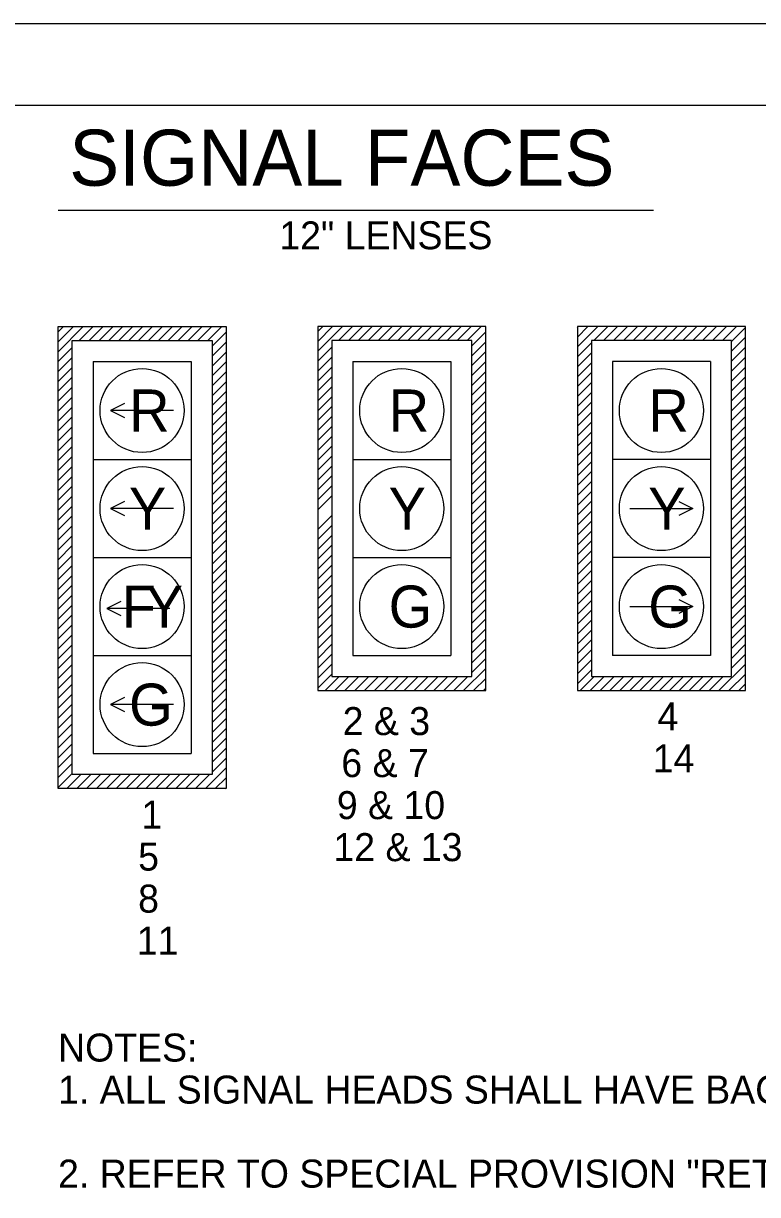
# Model space of a CAD drawing. Extents: x 659404 to 660404, y 642315 to 642955.
# Drawn here: x 659580.3 to 659685.2, y 642787.9 to 642955.1 of the extents above; entities that cross this region are included whole.
import ezdxf

# ---------------------------------------------------------------- set-up
doc = ezdxf.new("R2010")
doc.units = 0
for name, color, linetype in [('R_Border', 7, 'Continuous'), ('R_No Plot', 7, 'Continuous'), ('T_Drafting', 7, 'Continuous'), ('T_Notes', 7, 'Continuous')]:
    doc.layers.add(name, color=color, linetype=linetype)

msp = doc.modelspace()

# ---------------------------------------------------------------- linework, layer by layer
at = {"layer": 'R_Border'}
msp.add_line((659440.89, 642943.46), (660389.43, 642943.46), dxfattribs=at)
at = {"layer": 'R_No Plot'}
msp.add_line((659403.69, 642955.15), (660403.69, 642955.15), dxfattribs=at)
msp.add_lwpolyline([(659403.67, 642955.15), (660403.69, 642955.15), (660403.69, 642315.13), (659403.67, 642315.13)], close=True, dxfattribs=at)
at = {"layer": 'T_Drafting'}
for p, q in [((659585.24, 642845.87), (659585.24, 642911.87)), ((659585.24, 642911.87), (659609.24, 642911.87)), ((659585.24, 642908.27), (659588.85, 642911.87)), ((659585.24, 642909.68), (659587.44, 642911.87)), ((659585.24, 642911.09), (659586.02, 642911.87)), ((659588.26, 642909.87), (659590.26, 642911.87)), ((659589.68, 642909.87), (659591.68, 642911.87)), ((659591.09, 642909.87), (659593.09, 642911.87)), ((659592.51, 642909.87), (659594.51, 642911.87)), ((659593.92, 642909.87), (659595.92, 642911.87)), ((659595.33, 642909.87), (659597.33, 642911.87)), ((659596.75, 642909.87), (659598.75, 642911.87)), ((659598.16, 642909.87), (659600.16, 642911.87)), ((659599.58, 642909.87), (659601.58, 642911.87)), ((659600.99, 642909.87), (659602.99, 642911.87)), ((659602.41, 642909.87), (659604.41, 642911.87)), ((659603.82, 642909.87), (659605.82, 642911.87)), ((659605.23, 642909.87), (659607.23, 642911.87)), ((659606.65, 642909.87), (659608.65, 642911.87)), ((659609.24, 642911.87), (659609.24, 642845.87)), ((659646.34, 642911.87), (659622.34, 642911.87)), ((659622.34, 642911.87), (659622.34, 642859.87)), ((659622.34, 642908.33), (659625.88, 642911.87)), ((659622.34, 642909.74), (659624.47, 642911.87)), ((659622.34, 642911.15), (659623.05, 642911.87)), ((659625.3, 642909.87), (659627.3, 642911.87)), ((659626.71, 642909.87), (659628.71, 642911.87)), ((659628.12, 642909.87), (659630.12, 642911.87)), ((659629.54, 642909.87), (659631.54, 642911.87)), ((659630.95, 642909.87), (659632.95, 642911.87)), ((659632.37, 642909.87), (659634.37, 642911.87)), ((659633.78, 642909.87), (659635.78, 642911.87)), ((659635.2, 642909.87), (659637.2, 642911.87)), ((659636.61, 642909.87), (659638.61, 642911.87)), ((659638.02, 642909.87), (659640.02, 642911.87)), ((659639.44, 642909.87), (659641.44, 642911.87)), ((659640.85, 642909.87), (659642.85, 642911.87)), ((659642.27, 642909.87), (659644.27, 642911.87)), ((659643.68, 642909.87), (659645.68, 642911.87)), ((659646.34, 642859.87), (659646.34, 642911.87)), ((659683.43, 642911.87), (659659.43, 642911.87)), ((659659.43, 642911.87), (659659.43, 642859.87)), ((659659.43, 642908.95), (659662.35, 642911.87)), ((659659.43, 642910.36), (659660.94, 642911.87)), ((659659.43, 642911.78), (659659.52, 642911.87)), ((659661.77, 642909.87), (659663.77, 642911.87)), ((659663.18, 642909.87), (659665.18, 642911.87)), ((659664.6, 642909.87), (659666.6, 642911.87)), ((659666.01, 642909.87), (659668.01, 642911.87)), ((659667.42, 642909.87), (659669.42, 642911.87)), ((659668.84, 642909.87), (659670.84, 642911.87)), ((659670.25, 642909.87), (659672.25, 642911.87)), ((659671.67, 642909.87), (659673.67, 642911.87)), ((659673.08, 642909.87), (659675.08, 642911.87)), ((659674.5, 642909.87), (659676.5, 642911.87)), ((659675.91, 642909.87), (659677.91, 642911.87)), ((659677.32, 642909.87), (659679.32, 642911.87)), ((659678.74, 642909.87), (659680.74, 642911.87)), ((659680.15, 642909.87), (659682.15, 642911.87)), ((659681.43, 642909.73), (659683.43, 642911.73)), ((659683.43, 642859.87), (659683.43, 642911.87)), ((659607.24, 642909.05), (659609.24, 642911.05)), ((659607.24, 642907.64), (659609.24, 642909.64)), ((659644.34, 642909.11), (659646.34, 642911.11)), ((659644.34, 642907.7), (659646.34, 642909.7)), ((659659.43, 642907.53), (659661.43, 642909.53)), ((659681.43, 642908.32), (659683.43, 642910.32)), ((659585.24, 642906.85), (659587.24, 642908.85)), ((659607.24, 642906.22), (659609.24, 642908.22)), ((659622.34, 642906.91), (659624.34, 642908.91)), ((659644.34, 642906.28), (659646.34, 642908.28)), ((659659.43, 642906.12), (659661.43, 642908.12)), ((659681.43, 642906.91), (659683.43, 642908.91)), ((659585.24, 642905.44), (659587.24, 642907.44)), ((659590.24, 642906.87), (659604.24, 642906.87)), ((659590.24, 642906.87), (659590.24, 642892.87)), ((659604.24, 642906.87), (659604.24, 642892.87)), ((659607.24, 642904.81), (659609.24, 642906.81)), ((659622.34, 642905.5), (659624.34, 642907.5)), ((659627.34, 642906.87), (659641.34, 642906.87)), ((659627.34, 642906.87), (659627.34, 642892.87)), ((659641.34, 642906.87), (659641.34, 642892.87)), ((659644.34, 642904.87), (659646.34, 642906.87)), ((659659.43, 642904.7), (659661.43, 642906.7)), ((659678.43, 642906.87), (659664.43, 642906.87)), ((659664.43, 642906.87), (659664.43, 642892.87)), ((659678.43, 642906.87), (659678.43, 642892.87)), ((659681.43, 642905.49), (659683.43, 642907.49)), ((659585.24, 642904.02), (659587.24, 642906.02)), ((659585.24, 642902.61), (659587.24, 642904.61)), ((659607.24, 642903.4), (659609.24, 642905.4)), ((659622.34, 642904.08), (659624.34, 642906.08)), ((659622.34, 642902.67), (659624.34, 642904.67)), ((659644.34, 642903.46), (659646.34, 642905.46)), ((659659.43, 642903.29), (659661.43, 642905.29)), ((659681.43, 642904.08), (659683.43, 642906.08)), ((659681.43, 642902.66), (659683.43, 642904.66)), ((659585.24, 642901.19), (659587.24, 642903.19)), ((659607.24, 642901.98), (659609.24, 642903.98)), ((659622.34, 642901.25), (659624.34, 642903.25)), ((659644.34, 642902.04), (659646.34, 642904.04)), ((659659.43, 642901.88), (659661.43, 642903.88)), ((659681.43, 642901.25), (659683.43, 642903.25)), ((659585.24, 642899.78), (659587.24, 642901.78)), ((659607.24, 642900.57), (659609.24, 642902.57)), ((659607.24, 642899.15), (659609.24, 642901.15)), ((659622.34, 642899.84), (659624.34, 642901.84)), ((659644.34, 642900.63), (659646.34, 642902.63)), ((659644.34, 642899.21), (659646.34, 642901.21)), ((659659.43, 642900.46), (659661.43, 642902.46)), ((659681.43, 642899.83), (659683.43, 642901.83)), ((659585.24, 642898.37), (659587.24, 642900.37)), ((659601.74, 642899.87), (659592.74, 642899.87)), ((659607.24, 642897.74), (659609.24, 642899.74)), ((659622.34, 642898.43), (659624.34, 642900.43)), ((659644.34, 642897.8), (659646.34, 642899.8)), ((659659.43, 642899.05), (659661.43, 642901.05)), ((659659.43, 642897.63), (659661.43, 642899.63)), ((659681.43, 642898.42), (659683.43, 642900.42)), ((659585.24, 642896.95), (659587.24, 642898.95)), ((659607.24, 642896.32), (659609.24, 642898.32)), ((659622.34, 642897.01), (659624.34, 642899.01)), ((659644.34, 642896.38), (659646.34, 642898.38)), ((659659.43, 642896.22), (659661.43, 642898.22)), ((659681.43, 642897.01), (659683.43, 642899.01)), ((659585.24, 642895.54), (659587.24, 642897.54)), ((659607.24, 642894.91), (659609.24, 642896.91)), ((659622.34, 642895.6), (659624.34, 642897.6)), ((659622.34, 642894.18), (659624.34, 642896.18)), ((659644.34, 642894.97), (659646.34, 642896.97)), ((659659.43, 642894.8), (659661.43, 642896.8)), ((659681.43, 642895.59), (659683.43, 642897.59)), ((659681.43, 642894.18), (659683.43, 642896.18)), ((659585.24, 642894.12), (659587.24, 642896.12)), ((659585.24, 642892.71), (659587.24, 642894.71)), ((659607.24, 642893.5), (659609.24, 642895.5)), ((659622.34, 642892.77), (659624.34, 642894.77)), ((659644.34, 642893.56), (659646.34, 642895.56)), ((659659.43, 642893.39), (659661.43, 642895.39)), ((659681.43, 642892.76), (659683.43, 642894.76)), ((659585.24, 642891.29), (659587.24, 642893.29)), ((659590.24, 642892.87), (659604.24, 642892.87)), ((659590.24, 642892.87), (659590.24, 642878.87)), ((659604.24, 642892.87), (659604.24, 642878.87)), ((659607.24, 642892.08), (659609.24, 642894.08)), ((659622.34, 642891.35), (659624.34, 642893.35)), ((659627.34, 642892.87), (659641.34, 642892.87)), ((659627.34, 642892.87), (659627.34, 642878.87)), ((659641.34, 642892.87), (659641.34, 642878.87)), ((659644.34, 642892.14), (659646.34, 642894.14)), ((659659.43, 642891.98), (659661.43, 642893.98)), ((659678.43, 642892.87), (659664.43, 642892.87)), ((659664.43, 642892.87), (659664.43, 642878.87)), ((659678.43, 642892.87), (659678.43, 642878.87)), ((659681.43, 642891.35), (659683.43, 642893.35)), ((659585.24, 642889.88), (659587.24, 642891.88)), ((659607.24, 642890.67), (659609.24, 642892.67)), ((659607.24, 642889.25), (659609.24, 642891.25)), ((659622.34, 642889.94), (659624.34, 642891.94)), ((659644.34, 642890.73), (659646.34, 642892.73)), ((659644.34, 642889.31), (659646.34, 642891.31)), ((659659.43, 642890.56), (659661.43, 642892.56)), ((659659.43, 642889.15), (659661.43, 642891.15)), ((659681.43, 642889.93), (659683.43, 642891.93)), ((659585.24, 642888.47), (659587.24, 642890.47)), ((659607.24, 642887.84), (659609.24, 642889.84)), ((659622.34, 642888.53), (659624.34, 642890.53)), ((659644.34, 642887.9), (659646.34, 642889.9)), ((659659.43, 642887.73), (659661.43, 642889.73)), ((659681.43, 642888.52), (659683.43, 642890.52)), ((659585.24, 642887.05), (659587.24, 642889.05)), ((659607.24, 642886.42), (659609.24, 642888.42)), ((659622.34, 642887.11), (659624.34, 642889.11)), ((659644.34, 642886.48), (659646.34, 642888.48)), ((659659.43, 642886.32), (659661.43, 642888.32)), ((659681.43, 642887.11), (659683.43, 642889.11)), ((659585.24, 642885.64), (659587.24, 642887.64)), ((659585.24, 642884.22), (659587.24, 642886.22)), ((659607.24, 642885.01), (659609.24, 642887.01)), ((659622.34, 642885.7), (659624.34, 642887.7)), ((659644.34, 642885.07), (659646.34, 642887.07)), ((659659.43, 642884.91), (659661.43, 642886.91)), ((659681.43, 642885.69), (659683.43, 642887.69)), ((659681.43, 642884.28), (659683.43, 642886.28)), ((659585.24, 642882.81), (659587.24, 642884.81)), ((659601.74, 642885.87), (659592.74, 642885.87)), ((659607.24, 642883.6), (659609.24, 642885.6)), ((659622.34, 642882.87), (659624.34, 642884.87)), ((659644.34, 642883.66), (659646.34, 642885.66)), ((659659.43, 642883.49), (659661.43, 642885.49)), ((659666.93, 642885.87), (659675.93, 642885.87)), ((659681.43, 642882.86), (659683.43, 642884.86)), ((659585.24, 642881.4), (659587.24, 642883.4)), ((659607.24, 642882.18), (659609.24, 642884.18)), ((659607.24, 642880.77), (659609.24, 642882.77)), ((659622.34, 642881.46), (659624.34, 642883.46)), ((659644.34, 642882.24), (659646.34, 642884.24)), ((659644.34, 642880.83), (659646.34, 642882.83)), ((659659.43, 642882.08), (659661.43, 642884.08)), ((659681.43, 642881.45), (659683.43, 642883.45)), ((659585.24, 642879.98), (659587.24, 642881.98)), ((659607.24, 642879.35), (659609.24, 642881.35)), ((659622.34, 642880.04), (659624.34, 642882.04)), ((659644.34, 642879.41), (659646.34, 642881.41)), ((659659.43, 642880.66), (659661.43, 642882.66)), ((659659.43, 642879.25), (659661.43, 642881.25)), ((659681.43, 642880.04), (659683.43, 642882.04)), ((659585.24, 642878.57), (659587.24, 642880.57)), ((659607.24, 642877.94), (659609.24, 642879.94)), ((659622.34, 642878.63), (659624.34, 642880.63)), ((659644.34, 642878), (659646.34, 642880)), ((659659.43, 642877.83), (659661.43, 642879.83)), ((659681.43, 642878.62), (659683.43, 642880.62)), ((659585.24, 642877.15), (659587.24, 642879.15)), ((659585.24, 642875.74), (659587.24, 642877.74)), ((659590.24, 642878.87), (659604.24, 642878.87)), ((659590.24, 642878.87), (659590.24, 642864.87)), ((659604.24, 642878.87), (659604.24, 642864.87)), ((659607.24, 642876.52), (659609.24, 642878.52)), ((659622.34, 642877.21), (659624.34, 642879.21)), ((659622.34, 642875.8), (659624.34, 642877.8)), ((659627.34, 642878.87), (659641.34, 642878.87)), ((659627.34, 642878.87), (659627.34, 642864.87)), ((659641.34, 642878.87), (659641.34, 642864.87)), ((659644.34, 642876.59), (659646.34, 642878.59)), ((659659.43, 642876.42), (659661.43, 642878.42)), ((659678.43, 642878.87), (659664.43, 642878.87)), ((659664.43, 642878.87), (659664.43, 642864.87)), ((659678.43, 642878.87), (659678.43, 642864.87)), ((659681.43, 642877.21), (659683.43, 642879.21)), ((659681.43, 642875.79), (659683.43, 642877.79)), ((659585.24, 642874.32), (659587.24, 642876.32)), ((659607.24, 642875.11), (659609.24, 642877.11)), ((659622.34, 642874.38), (659624.34, 642876.38)), ((659644.34, 642875.17), (659646.34, 642877.17)), ((659659.43, 642875.01), (659661.43, 642877.01)), ((659681.43, 642874.38), (659683.43, 642876.38)), ((659585.24, 642872.91), (659587.24, 642874.91)), ((659607.24, 642873.7), (659609.24, 642875.7)), ((659622.34, 642872.97), (659624.34, 642874.97)), ((659644.34, 642873.76), (659646.34, 642875.76)), ((659659.43, 642873.59), (659661.43, 642875.59)), ((659681.43, 642872.96), (659683.43, 642874.96)), ((659585.24, 642871.5), (659587.24, 642873.5)), ((659607.24, 642872.28), (659609.24, 642874.28)), ((659607.24, 642870.87), (659609.24, 642872.87)), ((659622.34, 642871.56), (659624.34, 642873.56)), ((659644.34, 642872.34), (659646.34, 642874.34)), ((659644.34, 642870.93), (659646.34, 642872.93)), ((659659.43, 642872.18), (659661.43, 642874.18)), ((659659.43, 642870.76), (659661.43, 642872.76)), ((659681.43, 642871.55), (659683.43, 642873.55)), ((659585.24, 642870.08), (659587.24, 642872.08)), ((659601.22, 642871.59), (659592.22, 642871.59)), ((659607.24, 642869.45), (659609.24, 642871.45)), ((659622.34, 642870.14), (659624.34, 642872.14)), ((659644.34, 642869.51), (659646.34, 642871.51)), ((659659.43, 642869.35), (659661.43, 642871.35)), ((659666.93, 642871.87), (659675.93, 642871.87)), ((659681.43, 642870.14), (659683.43, 642872.14)), ((659585.24, 642868.67), (659587.24, 642870.67)), ((659607.24, 642868.04), (659609.24, 642870.04)), ((659622.34, 642868.73), (659624.34, 642870.73)), ((659644.34, 642868.1), (659646.34, 642870.1)), ((659659.43, 642867.93), (659661.43, 642869.93)), ((659681.43, 642868.72), (659683.43, 642870.72)), ((659585.24, 642867.25), (659587.24, 642869.25)), ((659585.24, 642865.84), (659587.24, 642867.84)), ((659607.24, 642866.63), (659609.24, 642868.63)), ((659622.34, 642867.31), (659624.34, 642869.31)), ((659622.34, 642865.9), (659624.34, 642867.9)), ((659644.34, 642866.69), (659646.34, 642868.69)), ((659659.43, 642866.52), (659661.43, 642868.52)), ((659681.43, 642867.31), (659683.43, 642869.31)), ((659681.43, 642865.89), (659683.43, 642867.89)), ((659585.24, 642864.42), (659587.24, 642866.42)), ((659607.24, 642865.21), (659609.24, 642867.21)), ((659622.34, 642864.48), (659624.34, 642866.48)), ((659644.34, 642865.27), (659646.34, 642867.27)), ((659659.43, 642865.11), (659661.43, 642867.11)), ((659681.43, 642864.48), (659683.43, 642866.48)), ((659585.24, 642863.01), (659587.24, 642865.01)), ((659590.24, 642864.87), (659604.24, 642864.87)), ((659590.24, 642864.87), (659590.24, 642850.87)), ((659604.24, 642864.87), (659604.24, 642850.87)), ((659607.24, 642863.8), (659609.24, 642865.8)), ((659607.24, 642862.38), (659609.24, 642864.38)), ((659622.34, 642863.07), (659624.34, 642865.07)), ((659627.34, 642864.87), (659641.34, 642864.87)), ((659644.34, 642863.86), (659646.34, 642865.86)), ((659644.34, 642862.44), (659646.34, 642864.44)), ((659659.43, 642863.69), (659661.43, 642865.69)), ((659678.43, 642864.87), (659664.43, 642864.87)), ((659681.43, 642863.06), (659683.43, 642865.06)), ((659585.24, 642861.6), (659587.24, 642863.6)), ((659607.24, 642860.97), (659609.24, 642862.97)), ((659622.34, 642861.66), (659624.34, 642863.66)), ((659643.18, 642859.87), (659646.34, 642863.03)), ((659659.43, 642862.28), (659661.43, 642864.28)), ((659659.43, 642860.86), (659661.43, 642862.86)), ((659679.65, 642859.87), (659683.43, 642863.65)), ((659585.24, 642860.18), (659587.24, 642862.18)), ((659607.24, 642859.55), (659609.24, 642861.55)), ((659622.34, 642860.24), (659624.34, 642862.24)), ((659623.38, 642859.87), (659625.38, 642861.87)), ((659624.79, 642859.87), (659626.79, 642861.87)), ((659626.21, 642859.87), (659628.21, 642861.87)), ((659627.62, 642859.87), (659629.62, 642861.87)), ((659629.04, 642859.87), (659631.04, 642861.87)), ((659630.45, 642859.87), (659632.45, 642861.87)), ((659631.86, 642859.87), (659633.86, 642861.87)), ((659633.28, 642859.87), (659635.28, 642861.87)), ((659634.69, 642859.87), (659636.69, 642861.87)), ((659636.11, 642859.87), (659638.11, 642861.87)), ((659637.52, 642859.87), (659639.52, 642861.87)), ((659638.94, 642859.87), (659640.94, 642861.87)), ((659640.35, 642859.87), (659642.35, 642861.87)), ((659641.76, 642859.87), (659643.76, 642861.87)), ((659644.59, 642859.87), (659646.34, 642861.61)), ((659659.85, 642859.87), (659661.85, 642861.87)), ((659661.26, 642859.87), (659663.26, 642861.87)), ((659662.68, 642859.87), (659664.68, 642861.87)), ((659664.09, 642859.87), (659666.09, 642861.87)), ((659665.51, 642859.87), (659667.51, 642861.87)), ((659666.92, 642859.87), (659668.92, 642861.87)), ((659668.34, 642859.87), (659670.34, 642861.87)), ((659669.75, 642859.87), (659671.75, 642861.87)), ((659671.16, 642859.87), (659673.16, 642861.87)), ((659672.58, 642859.87), (659674.58, 642861.87)), ((659673.99, 642859.87), (659675.99, 642861.87)), ((659675.41, 642859.87), (659677.41, 642861.87)), ((659676.82, 642859.87), (659678.82, 642861.87)), ((659678.24, 642859.87), (659680.24, 642861.87)), ((659681.06, 642859.87), (659683.43, 642862.24)), ((659585.24, 642858.77), (659587.24, 642860.77)), ((659585.24, 642857.35), (659587.24, 642859.35)), ((659607.24, 642858.14), (659609.24, 642860.14)), ((659622.34, 642859.87), (659646.34, 642859.87)), ((659646.01, 642859.87), (659646.34, 642860.2)), ((659659.43, 642859.87), (659683.43, 642859.87)), ((659682.48, 642859.87), (659683.43, 642860.82)), ((659585.24, 642855.94), (659587.24, 642857.94)), ((659601.74, 642857.87), (659592.74, 642857.87)), ((659607.24, 642856.73), (659609.24, 642858.73)), ((659585.24, 642854.52), (659587.24, 642856.52)), ((659607.24, 642855.31), (659609.24, 642857.31)), ((659585.24, 642853.11), (659587.24, 642855.11)), ((659607.24, 642853.9), (659609.24, 642855.9)), ((659607.24, 642852.48), (659609.24, 642854.48)), ((659585.24, 642851.7), (659587.24, 642853.7)), ((659607.24, 642851.07), (659609.24, 642853.07)), ((659585.24, 642850.28), (659587.24, 642852.28)), ((659607.24, 642849.65), (659609.24, 642851.65)), ((659585.24, 642848.87), (659587.24, 642850.87)), ((659585.24, 642847.45), (659587.24, 642849.45)), ((659590.24, 642850.87), (659604.24, 642850.87)), ((659607.24, 642848.24), (659609.24, 642850.24)), ((659585.24, 642846.04), (659587.24, 642848.04)), ((659586.49, 642845.87), (659588.49, 642847.87)), ((659587.9, 642845.87), (659589.9, 642847.87)), ((659589.32, 642845.87), (659591.32, 642847.87)), ((659590.73, 642845.87), (659592.73, 642847.87)), ((659592.15, 642845.87), (659594.15, 642847.87)), ((659593.56, 642845.87), (659595.56, 642847.87)), ((659594.97, 642845.87), (659596.97, 642847.87)), ((659596.39, 642845.87), (659598.39, 642847.87)), ((659597.8, 642845.87), (659599.8, 642847.87)), ((659599.22, 642845.87), (659601.22, 642847.87)), ((659600.63, 642845.87), (659602.63, 642847.87)), ((659602.05, 642845.87), (659604.05, 642847.87)), ((659603.46, 642845.87), (659605.46, 642847.87)), ((659604.87, 642845.87), (659606.87, 642847.87)), ((659606.29, 642845.87), (659609.24, 642848.83)), ((659607.7, 642845.87), (659609.24, 642847.41)), ((659609.12, 642845.87), (659609.24, 642846)), ((659609.24, 642845.87), (659585.24, 642845.87))]:
    msp.add_line(p, q, dxfattribs=at)
for points in [[(659587.24, 642847.87), (659587.24, 642909.87), (659607.24, 642909.87), (659607.24, 642847.87)], [(659644.34, 642861.87), (659644.34, 642909.87), (659624.34, 642909.87), (659624.34, 642861.87)], [(659681.43, 642909.87), (659661.43, 642909.87), (659661.43, 642861.87), (659681.43, 642861.87)]]:
    msp.add_lwpolyline(points, close=True, dxfattribs=at)
for points in [[(659594.74, 642900.87), (659592.74, 642899.87), (659594.74, 642898.87)], [(659594.74, 642886.87), (659592.74, 642885.87), (659594.74, 642884.87)], [(659673.93, 642886.87), (659675.93, 642885.87), (659673.93, 642884.87)], [(659673.93, 642872.87), (659675.93, 642871.87), (659673.93, 642870.87)], [(659594.22, 642872.59), (659592.22, 642871.59), (659594.22, 642870.59)], [(659594.74, 642858.87), (659592.74, 642857.87), (659594.74, 642856.87)]]:
    msp.add_lwpolyline(points, dxfattribs=at)
for centre in [(659597.24, 642899.87), (659634.34, 642899.87), (659671.43, 642899.87), (659597.24, 642885.87), (659634.34, 642885.87), (659671.43, 642885.87), (659597.24, 642871.87), (659634.34, 642871.87), (659671.43, 642871.87), (659597.24, 642857.87)]:
    msp.add_circle(centre, 6, dxfattribs=at)
at = {"layer": 'T_Notes'}
msp.add_line((659585.24, 642928.5), (659670.3, 642928.5), dxfattribs=at)

# ---------------------------------------------------------------- texts
at = {"layer": 'T_Drafting'}
msp.add_text('12" LENSES', height=4, rotation=0.072, dxfattribs=at).set_placement((659616.85, 642922.87))
for s, p in [('R', (659595.38, 642896.87)), ('R', (659632.47, 642896.87)), ('R', (659669.56, 642896.87)), ('Y', (659595.35, 642882.87)), ('Y', (659632.45, 642882.87)), ('Y', (659669.54, 642882.87)), ('F', (659594.34, 642868.87)), ('Y', (659597.76, 642868.87)), ('G', (659632.47, 642868.87)), ('G', (659669.56, 642868.87)), ('G', (659595.38, 642854.87))]:
    msp.add_text(s, height=6, dxfattribs=at).set_placement(p)
at = {"layer": 'T_Notes'}
for s, height, p in [('SIGNAL FACES', 8, (659586.84, 642931.97)), ('4', 4, (659670.87, 642854.19)), ('2 & 3', 4, (659625.9, 642853.52)), ('6 & 7', 4, (659625.71, 642847.52)), ('14', 4, (659670.2, 642848.19)), ('9 & 10', 4, (659625.07, 642841.52)), ('1', 4, (659597.15, 642840.17)), ('12 & 13', 4, (659624.58, 642835.52)), ('5', 4, (659596.68, 642834.17)), ('8', 4, (659596.68, 642828.17)), ('11', 4, (659596.49, 642822.17)), ('NOTES:', 4, (659585.24, 642806.9)), ('1. ALL SIGNAL HEADS SHALL HAVE BACKPLATES.', 4, (659585.24, 642800.9)), ('2. REFER TO SPECIAL PROVISION "RETROREFLECTIVE', 4, (659585.24, 642788.9))]:
    msp.add_text(s, height=height, dxfattribs=at).set_placement(p)

doc.saveas('drawing.dxf')
